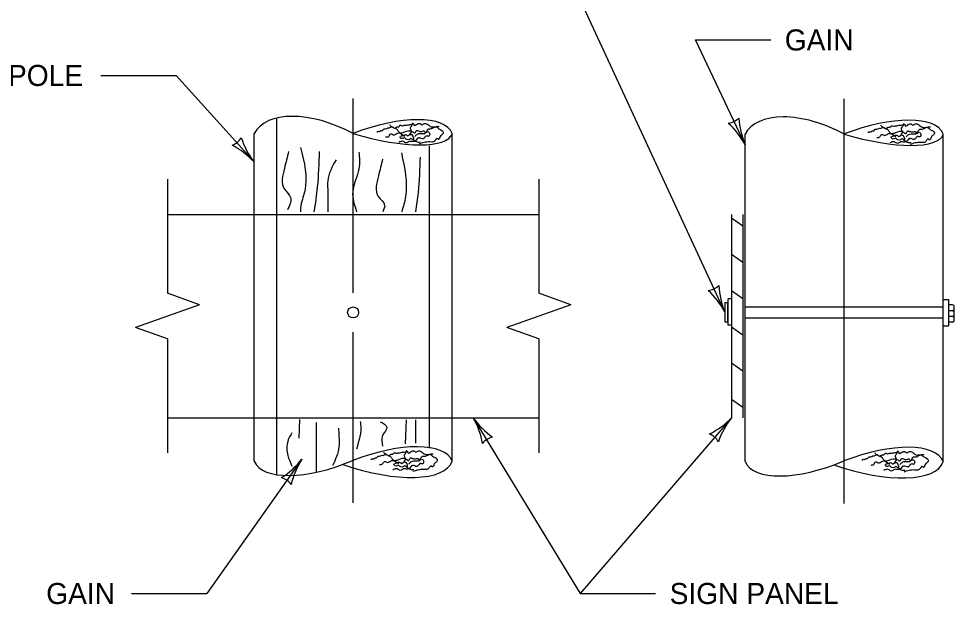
# Model space of a CAD drawing. Extents: x 49991.4 to 50021, y 49987.6 to 50011.4.
# Drawn here: x 50008.843 to 50011.509, y 49992.317 to 49993.987 of the extents above; entities that cross this region are included whole.
import ezdxf

# ---------------------------------------------------------------- set-up
doc = ezdxf.new("R2010")
doc.units = 0
for name, color, linetype in [('Level 1', 7, 'Continuous'), ('Level 2', 7, 'Continuous'), ('Level 3', 7, 'Continuous'), ('Level 4', 7, 'Continuous'), ('Level 5', 7, 'Continuous'), ('Level 6', 7, 'Continuous')]:
    doc.layers.add(name, color=color, linetype=linetype)

msp = doc.modelspace()

# ---------------------------------------------------------------- linework, layer by layer
at = {"layer": 'Level 1'}
for p, q in [((50009.5783, 49993.4288), (50009.5783, 49993.7016)), ((50009.5134, 49993.4287), (50009.5134, 49993.6593)), ((50010.0783, 49993.4287), (50010.0783, 49993.6593)), ((50010.913, 49992.7234), (50010.913, 49993.6578)), ((50011.4779, 49993.0191), (50011.4779, 49993.6577)), ((50010.0134, 49993.4309), (50010.0134, 49993.6242)), ((50009.2669, 49993.4287), (50010.3249, 49993.4287)), ((50010.8745, 49993.4187), (50010.907, 49993.3959)), ((50010.8745, 49993.3152), (50010.907, 49993.2924)), ((50010.8745, 49993.2118), (50010.907, 49993.189)), ((50010.8644, 49993.1127), (50010.8644, 49993.1879)), ((50010.8745, 49993.1879), (50010.8644, 49993.1879)), ((50011.4779, 49993.1863), (50011.4928, 49993.1863)), ((50011.4928, 49993.1863), (50011.4928, 49993.1111)), ((50011.5046, 49993.1702), (50011.4928, 49993.1702)), ((50011.5092, 49993.1538), (50011.4928, 49993.1538)), ((50011.5092, 49993.1261), (50011.5092, 49993.1656)), ((50011.5092, 49993.1375), (50011.4928, 49993.1375)), ((50011.5045, 49993.1213), (50011.4928, 49993.1213)), ((50010.8745, 49993.1127), (50010.8644, 49993.1127)), ((50010.8745, 49993.1083), (50010.907, 49993.0855)), ((50011.4779, 49993.1111), (50011.4928, 49993.1111)), ((50011.478, 49992.7234), (50011.4779, 49993.0191)), ((50010.8745, 49993.0049), (50010.907, 49992.9821)), ((50010.8745, 49992.9014), (50010.907, 49992.8786)), ((50009.2669, 49992.8486), (50010.3249, 49992.8486)), ((50009.5134, 49992.7248), (50009.5134, 49992.8486)), ((50009.5783, 49992.6863), (50009.5783, 49992.8486)), ((50009.643, 49992.8438), (50009.6409, 49992.7906)), ((50009.9471, 49992.8431), (50009.9444, 49992.7739)), ((50010.0134, 49992.7621), (50010.0134, 49992.8488)), ((50010.0783, 49992.725), (50010.0783, 49992.8486))]:
    msp.add_line(p, q, dxfattribs=at)
for points in [[(50010.8745, 49993.4287), (50010.8745, 49992.8486)], [(50010.9071, 49992.8486), (50010.9071, 49993.4287)]]:
    msp.add_lwpolyline(points, dxfattribs=at)
msp.add_lwpolyline([(50010.8636, 49993.1768), (50010.8551, 49993.1768), (50010.8551, 49993.1222), (50010.8636, 49993.1222)], close=True, dxfattribs=at)
msp.add_circle((50009.7959, 49993.1489), 0.0157, dxfattribs=at)
for centre, radius, start, end in [((50011.5046, 49993.1656), 0.0046, 0, 90), ((50011.5046, 49993.1584), 0.00459, 269.533, 359.533), ((50011.5044, 49993.149), 0.00483, 353.7489, 83.7489), ((50011.5046, 49993.1422), 0.00465, 269.4432, 359.4432), ((50011.5045, 49993.1328), 0.00472, 359.6397, 89.6397), ((50011.5045, 49993.1261), 0.00473, 269.9065, 359.9065)]:
    msp.add_arc(centre, radius, start, end, dxfattribs=at)
for centre, major_axis, ratio, start_param, end_param in [((50009.7326, 49993.5416), (-0.2192, 0.1177), 0.537084, 4.712389, 6.283185), ((50009.8326, 49993.5642), (0.2457, 0.0951), 0.387082, 0, 1.570796), ((50011.1322, 49993.5401), (-0.2192, 0.1177), 0.537049, 4.712389, 6.283507), ((50011.2323, 49993.5628), (0.2457, 0.0951), 0.387082, 0, 1.570796), ((50009.8198, 49993.7381), (0.2585, -0.0788), 0.304673, 4.712389, 6.283185), ((50011.2195, 49993.7366), (0.2585, -0.0788), 0.304673, 4.712389, 6.283185), ((50009.8326, 49992.6298), (0.2457, 0.0951), 0.395686, 0.000561, 1.570796), ((50011.2323, 49992.6283), (0.2457, 0.0951), 0.39576, 0, 1.570796), ((50009.753, 49992.8285), (-0.2396, -0.1036), 0.420526, 0.000916, 1.570796), ((50009.8017, 49992.8226), (0.2766, -0.0977), 0.384401, 4.720139, 6.283852), ((50011.1526, 49992.827), (-0.2396, -0.1036), 0.420526, 0, 1.564372), ((50011.2014, 49992.8212), (0.2766, -0.0977), 0.384401, 4.720139, 6.283185)]:
    msp.add_ellipse(centre, major_axis=major_axis, ratio=ratio, start_param=start_param, end_param=end_param, dxfattribs=at)
for points in [[(50009.8655, 49993.6625), (50009.8655, 49993.6654), (50009.8712, 49993.6654), (50009.8755, 49993.6683), (50009.8799, 49993.6683), (50009.8842, 49993.6726), (50009.8885, 49993.6726), (50009.8943, 49993.6755), (50009.8986, 49993.6755), (50009.9073, 49993.6783), (50009.9159, 49993.6741), (50009.9203, 49993.6783), (50009.926, 49993.6783), (50009.9303, 49993.6827), (50009.9376, 49993.6813), (50009.9418, 49993.6827), (50009.9462, 49993.6827), (50009.952, 49993.6841), (50009.9563, 49993.6841), (50009.9621, 49993.6856), (50009.9693, 49993.6856), (50009.9693, 49993.6827), (50009.9736, 49993.6827), (50009.9793, 49993.687), (50009.988, 49993.687), (50009.9923, 49993.6841), (50009.9966, 49993.687), (50010.0081, 49993.6856), (50010.0183, 49993.6783), (50010.0298, 49993.6783), (50010.0356, 49993.6769), (50010.0399, 49993.6726), (50010.0485, 49993.6683), (50010.0529, 49993.6611), (50010.0514, 49993.6582), (50010.0442, 49993.651), (50010.0384, 49993.6423), (50010.0356, 49993.6452), (50010.0298, 49993.6395), (50010.0226, 49993.6351), (50010.0139, 49993.6351), (50009.9981, 49993.6337), (50009.9837, 49993.6293)], [(50009.9433, 49993.651), (50009.926, 49993.664), (50009.9203, 49993.6712), (50009.9058, 49993.6783), (50009.9, 49993.6841)], [(50009.9577, 49993.6568), (50009.9621, 49993.6668), (50009.9592, 49993.6741), (50009.9635, 49993.6827), (50009.9663, 49993.6899)], [(50009.9721, 49993.651), (50009.9779, 49993.6568), (50009.9894, 49993.6596), (50010.0024, 49993.6611), (50010.0111, 49993.6726), (50010.0168, 49993.6726), (50010.0211, 49993.6741), (50010.0312, 49993.6783), (50010.0414, 49993.6798)], [(50011.2651, 49993.661), (50011.2651, 49993.6639), (50011.2709, 49993.6639), (50011.2752, 49993.6668), (50011.2796, 49993.6668), (50011.2839, 49993.6712), (50011.2882, 49993.6712), (50011.294, 49993.674), (50011.2983, 49993.674), (50011.3069, 49993.6769), (50011.3156, 49993.6726), (50011.3199, 49993.6769), (50011.3257, 49993.6769), (50011.33, 49993.6812), (50011.3372, 49993.6798), (50011.3415, 49993.6812), (50011.3459, 49993.6812), (50011.3517, 49993.6827), (50011.3559, 49993.6827), (50011.3617, 49993.6841), (50011.3689, 49993.6841), (50011.3689, 49993.6812), (50011.3732, 49993.6812), (50011.379, 49993.6855), (50011.3877, 49993.6855), (50011.392, 49993.6827), (50011.3963, 49993.6855), (50011.4078, 49993.6841), (50011.418, 49993.6769), (50011.4295, 49993.6769), (50011.4352, 49993.6754), (50011.4395, 49993.6712), (50011.4482, 49993.6668), (50011.4525, 49993.6596), (50011.4511, 49993.6567), (50011.4439, 49993.6495), (50011.4381, 49993.6409), (50011.4352, 49993.6437), (50011.4295, 49993.638), (50011.4222, 49993.6336), (50011.4136, 49993.6336), (50011.3977, 49993.6322), (50011.3834, 49993.6279)], [(50011.343, 49993.6495), (50011.3257, 49993.6625), (50011.3199, 49993.6697), (50011.3055, 49993.6769), (50011.2997, 49993.6827)], [(50011.3574, 49993.6553), (50011.3617, 49993.6654), (50011.3589, 49993.6726), (50011.3632, 49993.6812), (50011.366, 49993.6884)], [(50009.8885, 49993.6496), (50009.8972, 49993.651), (50009.903, 49993.6582), (50009.9116, 49993.6553), (50009.9203, 49993.6596), (50009.9332, 49993.6611), (50009.9433, 49993.664), (50009.9635, 49993.6654), (50009.9721, 49993.6611), (50009.9765, 49993.6683), (50009.9822, 49993.6668), (50009.9908, 49993.6654), (50009.9995, 49993.6654), (50010.001, 49993.6611), (50010.0067, 49993.664), (50010.0111, 49993.664), (50010.0139, 49993.6553), (50010.0111, 49993.651), (50010.0067, 49993.6524), (50010.001, 49993.6496), (50009.9952, 49993.6438), (50009.9822, 49993.6467), (50009.9736, 49993.638), (50009.9621, 49993.6366), (50009.9563, 49993.6366), (50009.9476, 49993.6323), (50009.939, 49993.6366), (50009.926, 49993.6337)], [(50009.9318, 49993.6524), (50009.9376, 49993.6538), (50009.9476, 49993.6553), (50009.9505, 49993.6524), (50009.9563, 49993.6553), (50009.9635, 49993.6553), (50009.9663, 49993.6409), (50009.9606, 49993.6452), (50009.9563, 49993.6423), (50009.9491, 49993.6423), (50009.9418, 49993.6467), (50009.9332, 49993.6452), (50009.9303, 49993.6481), (50009.9289, 49993.651)], [(50011.2882, 49993.6481), (50011.2969, 49993.6495), (50011.3026, 49993.6567), (50011.3113, 49993.6539), (50011.3199, 49993.6582), (50011.3329, 49993.6596), (50011.343, 49993.6625), (50011.3632, 49993.6639), (50011.3718, 49993.6596), (50011.3762, 49993.6668), (50011.3819, 49993.6654), (50011.3905, 49993.6639), (50011.3992, 49993.6639), (50011.4007, 49993.6596), (50011.4064, 49993.6625), (50011.4107, 49993.6625), (50011.4136, 49993.6539), (50011.4107, 49993.6495), (50011.4064, 49993.6509), (50011.4007, 49993.6481), (50011.3949, 49993.6423), (50011.3819, 49993.6452), (50011.3732, 49993.6366), (50011.3617, 49993.6351), (50011.3559, 49993.6351), (50011.3473, 49993.6308), (50011.3387, 49993.6351), (50011.3257, 49993.6322)], [(50011.3314, 49993.6509), (50011.3372, 49993.6524), (50011.3473, 49993.6539), (50011.3502, 49993.6509), (50011.3559, 49993.6539), (50011.3632, 49993.6539), (50011.366, 49993.6394), (50011.3603, 49993.6437), (50011.3559, 49993.6409), (50011.3487, 49993.6409), (50011.3415, 49993.6452), (50011.3329, 49993.6437), (50011.33, 49993.6467), (50011.3286, 49993.6495)], [(50011.3718, 49993.6495), (50011.3776, 49993.6553), (50011.3891, 49993.6582), (50011.4021, 49993.6596), (50011.4107, 49993.6712), (50011.4165, 49993.6712), (50011.4208, 49993.6726), (50011.4309, 49993.6769), (50011.441, 49993.6784)], [(50009.9678, 49993.6409), (50009.9779, 49993.6351), (50009.9866, 49993.6351)], [(50011.3675, 49993.6394), (50011.3776, 49993.6336), (50011.3862, 49993.6336)], [(50009.6118, 49993.6076), (50009.5999, 49993.56), (50009.5999, 49993.5005), (50009.6177, 49993.4768), (50009.6085, 49993.442)], [(50009.646, 49993.6196), (50009.6579, 49993.4947), (50009.646, 49993.4472), (50009.6455, 49993.4362)], [(50009.6995, 49993.6077), (50009.6936, 49993.5066), (50009.6843, 49993.4362)], [(50009.8124, 49993.6063), (50009.8124, 49993.5587), (50009.7946, 49993.4933), (50009.8059, 49993.4362)], [(50009.9333, 49993.6037), (50009.9452, 49993.4788), (50009.9345, 49993.4362)], [(50009.7471, 49993.5839), (50009.7233, 49993.5245), (50009.7233, 49993.5007), (50009.7233, 49993.4362)], [(50009.8798, 49993.5859), (50009.8679, 49993.5383), (50009.8679, 49993.4788), (50009.8857, 49993.4551), (50009.8807, 49993.4362)], [(50009.9868, 49993.5918), (50009.9808, 49993.4907), (50009.9737, 49993.4362)], [(50009.6908, 49992.8346), (50009.6908, 49992.8289), (50009.6908, 49992.7635), (50009.6908, 49992.7338), (50009.6908, 49992.7041), (50009.6908, 49992.6922)], [(50009.8158, 49992.8379), (50009.8169, 49992.8308), (50009.8051, 49992.7594)], [(50009.873, 49992.8373), (50009.8919, 49992.8216), (50009.88, 49992.7979), (50009.88, 49992.7677)], [(50009.9735, 49992.8426), (50009.9735, 49992.821), (50009.9735, 49992.776)], [(50009.6214, 49992.8058), (50009.6097, 49992.7823), (50009.6097, 49992.7407), (50009.6216, 49992.711)], [(50009.754, 49992.8188), (50009.7553, 49992.7953), (50009.7553, 49992.7656), (50009.7375, 49992.7121)], [(50009.8481, 49992.7284), (50009.8481, 49992.7314), (50009.8539, 49992.7314), (50009.8582, 49992.7342), (50009.8625, 49992.7342), (50009.8668, 49992.7386), (50009.8712, 49992.7386), (50009.877, 49992.7414), (50009.8813, 49992.7414), (50009.8899, 49992.7443), (50009.8986, 49992.74), (50009.9029, 49992.7443), (50009.9086, 49992.7443), (50009.913, 49992.7487), (50009.9202, 49992.7472), (50009.9245, 49992.7487), (50009.9288, 49992.7487), (50009.9346, 49992.7501), (50009.9389, 49992.7501), (50009.9447, 49992.7515), (50009.9519, 49992.7515), (50009.9519, 49992.7487), (50009.9562, 49992.7487), (50009.962, 49992.7529), (50009.9706, 49992.7529), (50009.975, 49992.7501), (50009.9793, 49992.7529), (50009.9908, 49992.7515), (50010.0009, 49992.7443), (50010.0124, 49992.7443), (50010.0182, 49992.7429), (50010.0225, 49992.7386), (50010.0311, 49992.7342), (50010.0355, 49992.727), (50010.0341, 49992.7241), (50010.0269, 49992.7169), (50010.0211, 49992.7083), (50010.0182, 49992.7111), (50010.0124, 49992.7054), (50010.0052, 49992.7011), (50009.9966, 49992.7011), (50009.9807, 49992.6996), (50009.9663, 49992.6953)], [(50009.926, 49992.7169), (50009.9086, 49992.7299), (50009.9029, 49992.7371), (50009.8885, 49992.7443), (50009.8827, 49992.7501)], [(50009.9403, 49992.7227), (50009.9447, 49992.7328), (50009.9418, 49992.74), (50009.9461, 49992.7487), (50009.949, 49992.7559)], [(50011.2478, 49992.727), (50011.2478, 49992.7299), (50011.2536, 49992.7299), (50011.2579, 49992.7327), (50011.2622, 49992.7327), (50011.2665, 49992.7371), (50011.2709, 49992.7371), (50011.2766, 49992.74), (50011.2809, 49992.74), (50011.2896, 49992.7428), (50011.2982, 49992.7385), (50011.3026, 49992.7428), (50011.3083, 49992.7428), (50011.3127, 49992.7472), (50011.3199, 49992.7457), (50011.3242, 49992.7472), (50011.3285, 49992.7472), (50011.3343, 49992.7486), (50011.3386, 49992.7486), (50011.3444, 49992.75), (50011.3516, 49992.75), (50011.3516, 49992.7472), (50011.3559, 49992.7472), (50011.3617, 49992.7515), (50011.3703, 49992.7515), (50011.3747, 49992.7486), (50011.379, 49992.7515), (50011.3905, 49992.75), (50011.4006, 49992.7428), (50011.4121, 49992.7428), (50011.4179, 49992.7414), (50011.4222, 49992.7371), (50011.4308, 49992.7327), (50011.4352, 49992.7255), (50011.4337, 49992.7227), (50011.4265, 49992.7155), (50011.4207, 49992.7068), (50011.4179, 49992.7097), (50011.4121, 49992.704), (50011.4049, 49992.6996), (50011.3962, 49992.6996), (50011.3804, 49992.6982), (50011.366, 49992.6938)], [(50011.3257, 49992.7155), (50011.3083, 49992.7285), (50011.3026, 49992.7357), (50011.2882, 49992.7428), (50011.2824, 49992.7486)], [(50011.34, 49992.7212), (50011.3444, 49992.7313), (50011.3415, 49992.7385), (50011.3458, 49992.7472), (50011.3487, 49992.7544)], [(50009.8712, 49992.7155), (50009.8798, 49992.7169), (50009.8856, 49992.7241), (50009.8943, 49992.7213), (50009.9029, 49992.7256), (50009.9158, 49992.727), (50009.926, 49992.7299), (50009.9461, 49992.7314), (50009.9548, 49992.727), (50009.9591, 49992.7342), (50009.9648, 49992.7328), (50009.9735, 49992.7314), (50009.9821, 49992.7314), (50009.9836, 49992.727), (50009.9894, 49992.7299), (50009.9937, 49992.7299), (50009.9966, 49992.7213), (50009.9937, 49992.7169), (50009.9894, 49992.7184), (50009.9836, 49992.7155), (50009.9778, 49992.7097), (50009.9648, 49992.7126), (50009.9562, 49992.704), (50009.9447, 49992.7025), (50009.9389, 49992.7025), (50009.9303, 49992.6982), (50009.9216, 49992.7025), (50009.9086, 49992.6996)], [(50009.9144, 49992.7184), (50009.9202, 49992.7198), (50009.9303, 49992.7213), (50009.9331, 49992.7184), (50009.9389, 49992.7213), (50009.9461, 49992.7213), (50009.949, 49992.7069), (50009.9433, 49992.7111), (50009.9389, 49992.7083), (50009.9317, 49992.7083), (50009.9245, 49992.7126), (50009.9158, 49992.7111), (50009.913, 49992.7141), (50009.9116, 49992.7169)], [(50009.9548, 49992.7169), (50009.9606, 49992.7227), (50009.9721, 49992.7256), (50009.9851, 49992.727), (50009.9937, 49992.7386), (50009.9995, 49992.7386), (50010.0038, 49992.74), (50010.0139, 49992.7443), (50010.024, 49992.7458)], [(50011.2709, 49992.714), (50011.2795, 49992.7155), (50011.2853, 49992.7227), (50011.2939, 49992.7198), (50011.3026, 49992.7241), (50011.3155, 49992.7255), (50011.3257, 49992.7285), (50011.3458, 49992.7299), (50011.3544, 49992.7255), (50011.3588, 49992.7327), (50011.3645, 49992.7313), (50011.3732, 49992.7299), (50011.3818, 49992.7299), (50011.3833, 49992.7255), (50011.389, 49992.7285), (50011.3934, 49992.7285), (50011.3962, 49992.7198), (50011.3934, 49992.7155), (50011.389, 49992.7169), (50011.3833, 49992.714), (50011.3775, 49992.7082), (50011.3645, 49992.7112), (50011.3559, 49992.7025), (50011.3444, 49992.701), (50011.3386, 49992.701), (50011.3299, 49992.6967), (50011.3213, 49992.701), (50011.3083, 49992.6982)], [(50011.3141, 49992.7169), (50011.3199, 49992.7183), (50011.3299, 49992.7198), (50011.3328, 49992.7169), (50011.3386, 49992.7198), (50011.3458, 49992.7198), (50011.3487, 49992.7054), (50011.3429, 49992.7097), (50011.3386, 49992.7068), (50011.3314, 49992.7068), (50011.3242, 49992.7112), (50011.3155, 49992.7097), (50011.3127, 49992.7126), (50011.3112, 49992.7155)], [(50011.3544, 49992.7155), (50011.3602, 49992.7212), (50011.3717, 49992.7241), (50011.3847, 49992.7255), (50011.3934, 49992.7371), (50011.3992, 49992.7371), (50011.4035, 49992.7385), (50011.4135, 49992.7428), (50011.4237, 49992.7443)], [(50009.9505, 49992.7069), (50009.9606, 49992.7011), (50009.9692, 49992.7011)], [(50011.3502, 49992.7054), (50011.3602, 49992.6996), (50011.3689, 49992.6996)]]:
    msp.add_spline(points, degree=3, dxfattribs=at)
at = {"layer": 'Level 3'}
for p, q in [((50010.8551, 49993.1495), (50010.3479, 49994.2482)), ((50010.913, 49993.6274), (50010.7714, 49993.9261)), ((50010.7714, 49993.9261), (50010.9861, 49993.9261)), ((50009.077, 49993.8249), (50009.2917, 49993.8249)), ((50009.2917, 49993.8249), (50009.5134, 49993.5784)), ((50010.138, 49992.8486), (50010.4433, 49992.3474)), ((50010.8745, 49992.8486), (50010.4433, 49992.3474)), ((50009.6496, 49992.7301), (50009.3788, 49992.3474)), ((50009.1641, 49992.3474), (50009.3788, 49992.3474)), ((50010.4433, 49992.3474), (50010.658, 49992.3474))]:
    msp.add_line(p, q, dxfattribs=at)
for centre, radius, start, end in [((50010.8578, 49993.7432), 0.0548, 277.6375, 313.3598), ((50010.7079, 49993.5169), 0.233, 28.326, 47.5758), ((50011.1174, 49993.7148), 0.2223, 182.9547, 203.1382), ((50009.4305, 49993.6762), 0.0548, 292.4439, 328.1663), ((50009.6887, 49993.7151), 0.2223, 197.7611, 217.9446), ((50009.3434, 49993.4191), 0.233, 43.1324, 62.3822), ((50010.8014, 49993.2659), 0.0548, 276.9186, 312.641), ((50010.6486, 49993.0416), 0.233, 27.6071, 46.8569), ((50011.0606, 49993.2343), 0.2223, 182.2358, 202.4193), ((50009.9457, 49992.7371), 0.2223, 9.9314, 30.1149), ((50010.3282, 49992.9833), 0.233, 215.3027, 234.5525), ((50010.7131, 49993.0016), 0.2223, 296.3542, 316.5377), ((50011.0574, 49992.7043), 0.233, 141.7255, 160.9754), ((50010.7902, 49992.752), 0.0548, 31.037, 66.7594), ((50010.2068, 49992.7405), 0.0548, 104.6142, 140.3366), ((50009.474, 49992.8665), 0.2223, 301.9846, 322.1681), ((50009.8458, 49992.6045), 0.233, 147.3559, 166.6058), ((50009.5752, 49992.6257), 0.0548, 36.6674, 72.3898)]:
    msp.add_arc(centre, radius, start, end, dxfattribs=at)
at = {"layer": 'Level 4'}
for p, q in [((50009.5134, 49992.8486), (50009.5134, 49993.4269)), ((50009.5783, 49992.8486), (50009.5783, 49993.4288)), ((50010.0134, 49992.8488), (50010.0134, 49993.4309)), ((50010.0783, 49992.8486), (50010.0783, 49993.4287)), ((50010.913, 49993.1646), (50011.4779, 49993.1646)), ((50010.913, 49993.1331), (50011.4779, 49993.1331))]:
    msp.add_line(p, q, dxfattribs=at)
at = {"layer": 'Level 5'}
for p, q in [((50009.7959, 49993.2046), (50009.7959, 49993.7593)), ((50011.1955, 49992.6044), (50011.1955, 49993.7578)), ((50009.7959, 49992.6058), (50009.7959, 49993.0931))]:
    msp.add_line(p, q, dxfattribs=at)
at = {"layer": 'Level 6'}
for p, q in [((50009.2669, 49993.5287), (50009.2669, 49993.2035)), ((50010.3249, 49993.5287), (50010.3249, 49993.2035)), ((50009.3583, 49993.1711), (50009.2669, 49993.2035)), ((50010.4163, 49993.1711), (50010.3249, 49993.2035)), ((50009.3583, 49993.1711), (50009.2669, 49993.1387)), ((50010.4163, 49993.1711), (50010.3249, 49993.1387)), ((50009.2669, 49993.1387), (50009.1755, 49993.1063)), ((50010.3249, 49993.1387), (50010.2335, 49993.1063)), ((50009.2669, 49993.0739), (50009.1755, 49993.1063)), ((50010.3249, 49993.0739), (50010.2335, 49993.1063)), ((50009.2669, 49993.0739), (50009.2669, 49992.7486)), ((50010.3249, 49993.0739), (50010.3249, 49992.7486))]:
    msp.add_line(p, q, dxfattribs=at)

# ---------------------------------------------------------------- texts
at = {"layer": 'Level 2'}
for s, p in [('GAIN', (50011.0261, 49993.8961)), ('WOOD POLE', (50008.5313, 49993.7949)), ('GAIN', (50008.9211, 49992.3174)), ('SIGN PANEL', (50010.698, 49992.3174))]:
    msp.add_text(s, height=0.06, dxfattribs=at).set_placement(p)

doc.saveas('drawing.dxf')
